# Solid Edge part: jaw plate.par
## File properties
Title: Jaw Plate
Author: Deepak Maini
Template: Normal.par
Last saved by: Robert a Rhodes jr
Revision: 7
Application: Solid Edge
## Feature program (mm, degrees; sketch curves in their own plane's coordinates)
sketch for "unnamed Protrusion 1" plane through (0, 0, 0) normal (0, -1, 0) x-axis (1, 0, 0)
  line (-34.925, 22.225) -> (34.925, 22.225)
  line (34.925, 22.225) -> (34.925, -22.225)
  line (34.925, -22.225) -> (-34.925, -22.225)
  line (-34.925, -22.225) -> (-34.925, 22.225)
extrude "unnamed Protrusion 1" add finite 4.7498 symmetric
sketch for "unnamed Hole 1" plane through (0, -2.3749, 0) normal (0, -1, 0) x-axis (1, 0, 0)
  hole centre (19.05, 3.175) bore radius 3.175
hole "unnamed Hole 1" through
sketch for "unnamed Hole 2" plane through (0, -2.3749, 0) normal (0, -1, 0) x-axis (1, 0, 0)
  hole centre (-19.05, 3.175) bore radius 3.175
  dimension (linear) = 19.05
  dimension (linear) = 19.05
hole "unnamed Hole 2" through
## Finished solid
Body 1: solid body, 6 faces, 12 edges, 8 vertices.
  Faces by surface: plane 6
  Edges by curve: line 12
Bounding box of the edges (mm): 69.850 x 4.750 x 44.450, from (-34.925, -2.3749, -22.225) to (34.925, 2.3749, 22.225).
Planar faces by outward normal: +x 1, +y 1, +z 1, -x 1, -y 1, -z 1
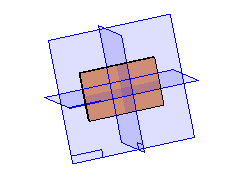
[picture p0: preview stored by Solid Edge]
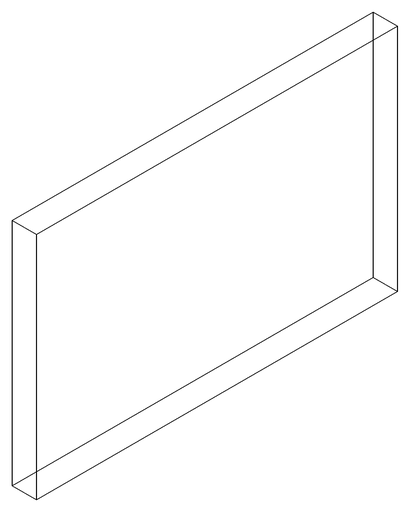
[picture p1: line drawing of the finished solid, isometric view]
